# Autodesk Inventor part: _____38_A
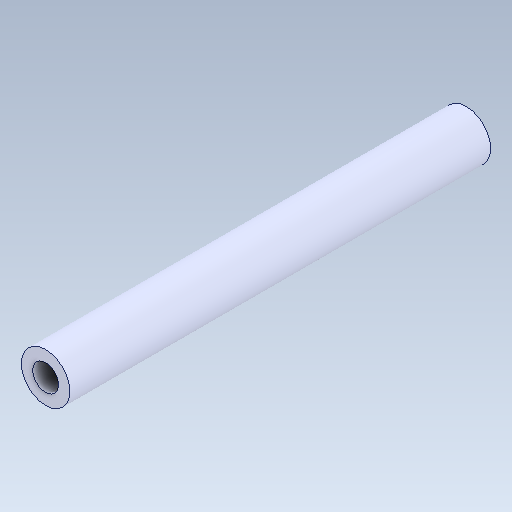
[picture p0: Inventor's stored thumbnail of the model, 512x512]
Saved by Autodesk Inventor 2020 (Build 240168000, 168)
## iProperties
Created: 2017-09
Part Number: _____38_A
Material: Générique
Document SubType Name: Modeling
Designer: bruno
Density: 1 g/cm^3
Appearance: Par défaut
Author: bruno
Sending System: SolidWorks 2016
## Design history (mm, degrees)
feature "Importée1"
node "Solide1"
